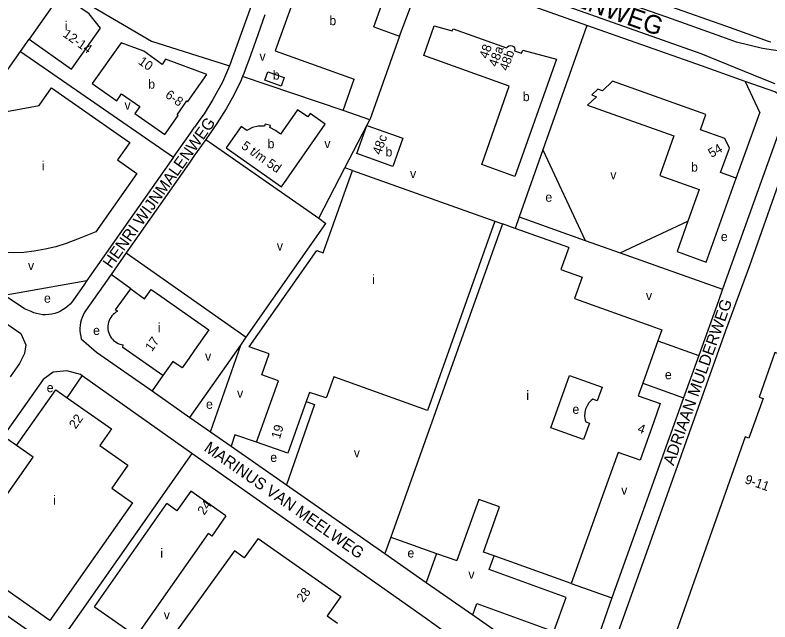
# Model space of a CAD drawing. Extents: x 154765 to 156627, y 383996 to 386132.
# Drawn here: x 155422.2 to 155749.2, y 384900.8 to 385163.7 of the extents above; entities that cross this region are included whole.
import ezdxf

# ---------------------------------------------------------------- set-up
doc = ezdxf.new("R2010")
doc.units = 0
for name, color, linetype in [('BLT_Basislijn', 7, 'Continuous'), ('BLT_Bebouwing', 7, 'Continuous'), ('BLT_Centroide', 7, 'Continuous'), ('BLT_Huisnummer', 7, 'Continuous'), ('BLT_Huisnummer_reeks', 7, 'Continuous'), ('BLT_Onderverdeling_panden', 7, 'Continuous'), ('BLT_Straatnaam', 7, 'Continuous'), ('BLT_Straatnaam_hoofdweg', 7, 'Continuous')]:
    doc.layers.add(name, color=color, linetype=linetype)

msp = doc.modelspace()

# ---------------------------------------------------------------- linework, layer by layer
at = {"layer": 'BLT_Basislijn'}
for p, q in [((155531.64, 385187.95), (155515.19, 385141.8)), ((155588.82, 385154.61), (155599.94, 385184.14)), ((155669.92, 385159.28), (155650.93, 385105.4)), ((155424.54, 385148.02), (155490.88, 385102.21)), ((155564.35, 385122.44), (155520.8, 385137.06)), ((155738.57, 385134.96), (155744.9, 385121.39)), ((155574.61, 385115.89), (155575.94, 385118.32)), ((155755.51, 385119.74), (155728.73, 385044.96)), ((155734.56, 385093.08), (155744.9, 385121.39)), ((155565.13, 385097.53), (155574.61, 385115.89)), ((155504.83, 385109.89), (155553.86, 385075.7)), ((155759.38, 385109.1), (155740.4, 385055.14)), ((155650.93, 385105.4), (155640.67, 385076.31)), ((155650.93, 385105.4), (155669.23, 385066.14)), ((155553.86, 385075.7), (155565.13, 385097.53)), ((155568.46, 385096.34), (155565.13, 385097.53)), ((155640.67, 385076.31), (155638.92, 385071.32)), ((155640.67, 385076.31), (155669.23, 385066.14)), ((155522.39, 385024.22), (155556.91, 385073.48)), ((155553.86, 385075.7), (155556.91, 385073.48)), ((155630.02, 385074.4), (155633.33, 385073.31)), ((155684.36, 385060.76), (155713.72, 385074.45)), ((155669.23, 385066.14), (155684.36, 385060.76)), ((155470.39, 385060.75), (155522.39, 385024.22)), ((155684.36, 385060.76), (155728.73, 385044.96)), ((155740.4, 385055.14), (155730.06, 385026.91)), ((155472.35, 385045.11), (155463.8, 385051.33)), ((155417.54, 385042.4), (155453.37, 385048.72)), ((155728.73, 385044.96), (155726.94, 385039.98)), ((155726.94, 385039.98), (155718.46, 385016.3)), ((155520, 385020.8), (155522.39, 385024.22)), ((155498, 384989.42), (155520, 385020.8)), ((155700.72, 385022.61), (155718.46, 385016.3)), ((155718.46, 385016.3), (155711.88, 384997.92)), ((155444.72, 384997.98), (155451.34, 385007.42)), ((155486.24, 385007.56), (155481.59, 385000.88)), ((155694.17, 385004.22), (155711.88, 384997.92)), ((155711.88, 384997.92), (155680.83, 384911.21)), ((155717.36, 384991.32), (155685.56, 384902.17)), ((155498, 384989.42), (155506.89, 384983.21)), ((155422.86, 384977.28), (155417.1, 384981.32)), ((155506.89, 384983.21), (155515.79, 384977)), ((155515.79, 384977), (155539.81, 384960.22)), ((155498.87, 384973.86), (155439.29, 384888.96)), ((155539.81, 384960.22), (155582.46, 384930.42)), ((155585.01, 384937.57), (155582.46, 384930.42)), ((155604.84, 384930.5), (155600.36, 384917.92)), ((155663.21, 384917.49), (155680.83, 384911.21)), ((155680.83, 384911.21), (155671.48, 384885.12))]:
    msp.add_line(p, q, dxfattribs=at)
for points in [[(155558.69, 385204.04), (155671.59, 385164), (155719.27, 385147.11), (155745.95, 385136.27), (155751.44, 385134.14)], [(155669.92, 385159.28), (155620.24, 385176.93), (155599.94, 385184.14)], [(155755.57, 385147.79), (155746.1, 385149.29), (155734.81, 385152.01), (155728.35, 385154.34), (155704.53, 385162.79), (155673.76, 385173.72)], [(155454.45, 385168.14), (155481.31, 385152.46), (155515.19, 385141.8)], [(155706.21, 385167.51), (155730.03, 385159.05), (155748.54, 385152.39), (155749.64, 385152.13)], [(155530.45, 385163.87), (155526.46, 385152.67), (155523.46, 385144.21), (155522.69, 385142.05)], [(155738.57, 385134.96), (155717.6, 385142.4), (155669.92, 385159.28)], [(155515.19, 385141.8), (155512.08, 385134.61), (155507.88, 385127.15), (155504.08, 385121.01), (155503.18, 385119.65), (155500, 385115.17)], [(155522.69, 385142.05), (155521.4, 385138.49), (155520.8, 385137.06)], [(155520.8, 385137.06), (155520.02, 385135.19), (155517.04, 385129.07), (155513.64, 385123.17), (155509.68, 385116.82)], [(155755.7, 385127.53), (155751.4, 385130.42), (155738.57, 385134.96)], [(155490.88, 385102.21), (155498.16, 385112.57), (155500, 385115.17)], [(155509.68, 385116.82), (155504.83, 385109.89)], [(155504.83, 385109.89), (155500, 385103)], [(155490.88, 385102.21), (155453.37, 385048.72)], [(155500, 385103), (155497.89, 385100), (155497.6, 385099.61), (155475.78, 385068.49), (155470.39, 385060.75)], [(155470.39, 385060.75), (155463.8, 385051.33)], [(155463.8, 385051.33), (155452.76, 385035.61)], [(155453.37, 385048.72), (155451.96, 385046.71), (155447.5, 385040.32)], [(155426.24, 385036.42), (155417.54, 385042.4)], [(155447.5, 385040.32), (155446.81, 385039.39), (155446.02, 385038.49), (155445.14, 385037.64), (155444.17, 385036.84), (155443.1, 385036.11), (155441.96, 385035.47), (155440.74, 385034.93), (155439.47, 385034.49), (155438.16, 385034.17), (155436.82, 385033.97), (155435.47, 385033.89), (155434.12, 385033.94), (155432.8, 385034.11), (155431.52, 385034.39), (155430.29, 385034.77), (155429.13, 385035.25), (155426.24, 385036.42)], [(155452.76, 385035.61), (155452.21, 385034.7), (155451.7, 385033.73), (155451.27, 385032.7), (155450.91, 385031.61), (155450.63, 385030.49), (155450.44, 385029.32), (155450.34, 385028.13), (155450.34, 385026.92), (155450.45, 385025.72), (155450.65, 385024.52), (155450.92, 385023.48)], [(155414.13, 385033.17), (155418.65, 385030.02), (155424.69, 385025.76), (155426.85, 385020.91), (155426.31, 385017.14), (155424.15, 385012.83), (155420.04, 385007.04)], [(155730.06, 385026.91), (155717.36, 384991.32)], [(155450.92, 385023.48), (155457.54, 385017.68), (155481.59, 385000.88)], [(155506.89, 384983.21), (155520, 385020.8)], [(155451.34, 385007.42), (155450.54, 385007.98), (155444.62, 385009.6), (155438.7, 385009.06), (155434.39, 385005.82), (155417.1, 384981.32)], [(155498.87, 384973.86), (155451.34, 385007.42)], [(155481.59, 385000.88), (155498, 384989.42)], [(155548.35, 384996.35), (155551.97, 384995.09), (155539.81, 384960.22)], [(155526.82, 384978.65), (155517.5, 384981.9), (155515.79, 384977)], [(155607.31, 384897.29), (155600, 384902.45), (155498.87, 384973.86)], [(155582.46, 384930.42), (155600.36, 384917.92)], [(155620.48, 384903.87), (155622.3, 384908.85), (155655.58, 384896.67), (155660.96, 384911.36), (155627.69, 384923.55), (155629.83, 384929.4)], [(155600.36, 384917.92), (155620.48, 384903.87)], [(155620.48, 384903.87), (155651.95, 384881.89)], [(155685.56, 384902.17), (155677.57, 384880.07), (155673.46, 384870.93), (155666.12, 384858.04)]]:
    msp.add_lwpolyline(points, dxfattribs=at)
at = {"layer": 'BLT_Bebouwing'}
for p, q in [((155599.26, 385146.25), (155603.8, 385159.03)), ((155603.8, 385159.03), (155611.64, 385156.96)), ((155611.64, 385156.96), (155611.95, 385157.79)), ((155400, 385113.29), (155424.54, 385148.02)), ((155534.94, 385148.2), (155569.18, 385136.03)), ((155642.14, 385148.51), (155656.82, 385144.69)), ((155636.29, 385132.98), (155599.26, 385146.25)), ((155624.37, 385098.99), (155636.29, 385132.98)), ((155638.8, 385093.86), (155624.37, 385098.99)), ((155741.73, 384984.41), (155741.74, 384984.4)), ((155456.67, 384907.42), (155487.98, 384952.08)), ((155492.36, 384949.02), (155487.98, 384952.08)), ((155513.59, 384946.77), (155507.46, 384938.03)), ((155507.46, 384938.03), (155505.97, 384939.07)), ((155527.47, 384937.04), (155521.5, 384928.6)), ((155527.47, 384937.04), (155541.11, 384927.49)), ((155517.23, 384931.68), (155485.23, 384887.36)), ((155521.5, 384928.6), (155517.23, 384931.68)), ((155541.11, 384927.49), (155563.37, 384911.88)), ((155563.37, 384911.88), (155557.44, 384903.43)), ((155557.44, 384903.43), (155561.85, 384900.33))]:
    msp.add_line(p, q, dxfattribs=at)
for points in [[(155577.59, 385158.61), (155581.82, 385170.48), (155574.93, 385172.93), (155575.55, 385174.67), (155553.22, 385182.59), (155551.44, 385182.95)], [(155428.3, 385153.34), (155446.72, 385140.34), (155459.18, 385158.04), (155454.27, 385164.27), (155442.01, 385172.85)], [(155542.97, 385170.82), (155534.94, 385148.2)], [(155577.59, 385158.61), (155588.82, 385154.61)], [(155611.95, 385157.79), (155635.18, 385149.48), (155635.51, 385149.99), (155636.14, 385150.43), (155636.95, 385150.58), (155637.59, 385150.43), (155638.16, 385150.05), (155638.54, 385149.5), (155638.7, 385148.82), (155638.63, 385148.24), (155641.65, 385147.16)], [(155588.82, 385154.61), (155575.94, 385118.32)], [(155424.54, 385148.02), (155428.3, 385153.34)], [(155468.14, 385151.74), (155455.67, 385134.02), (155466.24, 385126.61), (155468.35, 385129.61), (155476.24, 385124.07), (155474.13, 385121.07), (155487.09, 385111.95), (155492.83, 385120.16), (155492.42, 385120.45), (155496.68, 385126.52), (155497.09, 385126.24), (155505.27, 385137.93)], [(155505.27, 385137.93), (155487.45, 385144.59), (155485.93, 385142.38), (155478.07, 385148.08), (155468.14, 385151.74)], [(155641.65, 385147.16), (155642.14, 385148.51)], [(155656.82, 385144.69), (155638.8, 385093.86)], [(155564.35, 385122.44), (155569.18, 385136.03)], [(155734.56, 385093.08), (155727.91, 385095.51), (155731.69, 385106.03), (155729.74, 385110.24), (155719.12, 385114.03), (155721.45, 385120.7), (155681.04, 385135.1), (155676.67, 385130.92), (155674.66, 385131.64), (155672.13, 385129.15), (155674.13, 385128.38), (155670.19, 385124.72), (155707.61, 385111.35), (155701.5, 385094.26), (155718.59, 385088.15), (155713.72, 385074.45)], [(155400, 385104.36), (155411.43, 385120.68), (155432.67, 385124.51), (155438.05, 385132.17), (155467.8, 385111.44), (155471.9, 385108.58), (155466.59, 385100.99), (155474.93, 385095.15), (155457.22, 385069.83), (155449.21, 385066.66), (155444.34, 385064.78), (155439.85, 385063.36), (155435.29, 385062.31), (155430.51, 385061.49), (155425.98, 385060.94), (155421.34, 385060.7), (155415.6, 385060.82), (155407.39, 385061.04), (155400, 385066.22)], [(155556.6, 385116.46), (155550.12, 385121.11), (155549.06, 385119.62), (155544.65, 385122.72), (155537.25, 385112.15), (155535.03, 385113.71), (155532.59, 385115.02), (155532.82, 385115.92), (155530.57, 385116.49), (155530.34, 385115.58), (155527.58, 385115.59), (155525.05, 385115), (155522.7, 385113.79), (155520.24, 385115.51), (155513.68, 385106.18)], [(155575.94, 385118.32), (155564.35, 385122.44)], [(155513.68, 385106.18), (155537.67, 385089.36), (155556.6, 385116.46)], [(155526.82, 384978.65), (155536.34, 385005.32), (155529.1, 385007.89), (155532.32, 385016.92), (155523.71, 385020.02), (155553.01, 385061.73), (155555.77, 385060.74), (155568.46, 385096.34)], [(155568.46, 385096.34), (155630.02, 385074.4)], [(155721.61, 385056.68), (155734.56, 385093.08)], [(155630.02, 385074.4), (155600.84, 384992.48), (155560.29, 385006.95), (155557.42, 384998.96), (155557.05, 384997.91), (155549.74, 385000.25), (155548.35, 384996.35)], [(155633.33, 385073.31), (155585.01, 384937.57)], [(155638.92, 385071.32), (155633.33, 385073.31)], [(155713.72, 385074.45), (155709.03, 385061.25), (155721.61, 385056.68)], [(155662.07, 385063.08), (155638.92, 385071.32)], [(155662.07, 385063.08), (155658.67, 385053.54), (155667.97, 385050.22), (155664.65, 385040.89), (155697.72, 385029.07), (155702.43, 385027.39), (155700.72, 385022.61)], [(155466.6, 385035.36), (155465.73, 385036), (155472.35, 385045.11)], [(155472.35, 385045.11), (155478.29, 385040.79), (155481.22, 385044.81), (155485.32, 385041.94), (155500, 385031.65), (155506.17, 385027.32), (155500, 385018.51), (155497.5, 385014.95), (155494.63, 385010.85), (155490.53, 385013.72), (155486.24, 385007.56)], [(155762.36, 385042.82), (155753.18, 385017), (155751.43, 385017.62), (155744.64, 384998.23), (155746.3, 384997.64), (155740.17, 384980.4), (155738.59, 384980.96), (155696.77, 384862.93)], [(155466.6, 385035.36), (155465.92, 385034.97), (155465.29, 385034.51), (155464.7, 385033.99), (155464.17, 385033.41), (155463.69, 385032.78), (155463.29, 385032.11), (155462.96, 385031.4), (155462.7, 385030.66), (155462.51, 385029.89), (155462.41, 385029.12), (155462.38, 385028.33), (155462.44, 385027.55), (155462.57, 385026.77), (155462.79, 385026.02), (155463.07, 385025.29), (155463.43, 385024.59), (155463.87, 385023.93), (155464.36, 385023.32), (155464.91, 385022.77), (155465.52, 385022.27), (155466.18, 385021.84), (155466.87, 385021.47), (155467.6, 385021.18), (155468.36, 385020.97), (155469.03, 385020.84)], [(155486.24, 385007.56), (155468.91, 385019.67), (155469.03, 385020.84)], [(155700.72, 385022.61), (155694.17, 385004.22)], [(155669.45, 384987.57), (155671.08, 384986.96), (155668.55, 384979.8), (155654.33, 384984.85), (155662.39, 385007.58), (155676.58, 385002.55), (155674.46, 384996.55), (155672.6, 384997.28)], [(155694.17, 385004.22), (155692.67, 385000), (155692.24, 384998.8), (155701.77, 384995.41), (155698.94, 384987.5), (155693.01, 384970.89), (155683.48, 384974.23), (155677.32, 384957.01), (155663.21, 384917.49)], [(155422.86, 384977.28), (155439.82, 385001.42)], [(155439.82, 385001.42), (155444.72, 384997.98)], [(155444.72, 384997.98), (155463.95, 384984.47), (155458.92, 384977.32), (155471.07, 384968.79), (155464.07, 384958.83), (155473.14, 384952.46), (155437.27, 384901.4), (155412.17, 384919.04), (155417.32, 384926.36), (155404.26, 384935.53), (155430.04, 384972.23), (155422.86, 384977.28)], [(155672.6, 384997.28), (155671.87, 384996.76), (155670.87, 384995.73), (155670.01, 384994.48), (155669.35, 384992.94), (155669.02, 384991.49), (155668.95, 384989.96), (155669.21, 384988.28), (155669.45, 384987.57)], [(155548.35, 384996.35), (155540.35, 384973.93), (155526.82, 384978.65)], [(155513.59, 384946.77), (155498.3, 384957.49), (155492.36, 384949.02)], [(155629.83, 384929.4), (155625.14, 384931.07), (155632.16, 384950.76), (155623.21, 384953.94), (155613.59, 384927.39)], [(155456.67, 384907.42), (155474.83, 384894.65), (155505.97, 384939.07)], [(155585.01, 384937.57), (155604.84, 384930.5)], [(155604.84, 384930.5), (155613.59, 384927.39)], [(155663.21, 384917.49), (155629.83, 384929.4)], [(155439.29, 384888.96), (155399.36, 384917.11)]]:
    msp.add_lwpolyline(points, dxfattribs=at)
for points in [[(155530.4, 385135.47), (155531.74, 385139.17), (155538.86, 385136.63), (155537.52, 385132.91)], [(155574.61, 385115.89), (155590.21, 385110.34), (155585.86, 385098.13), (155570.26, 385103.71)]]:
    msp.add_lwpolyline(points, close=True, dxfattribs=at)
at = {"layer": 'BLT_Onderverdeling_panden'}
msp.add_line((155442.01, 385172.85), (155428.3, 385153.34), dxfattribs=at)

# ---------------------------------------------------------------- texts
at = {"layer": 'BLT_Centroide'}
for s, p in [('i', (155443.73, 385157.05)), ('b', (155558.38, 385159.36)), ('v', (155528.1, 385143.93)), ('b', (155533.89, 385135.78)), ('b', (155479.9, 385131.84)), ('b', (155642.17, 385126.44)), ('v', (155469.62, 385122.8)), ('b', (155531.6, 385106.03)), ('v', (155556.2, 385106.09)), ('b', (155582.71, 385102.5)), ('i', (155433.77, 385096.44)), ('b', (155715.07, 385095.91)), ('v', (155593.32, 385093.08)), ('v', (155680.08, 385092.59)), ('e', (155651.97, 385082.86)), ('e', (155727.99, 385065.81)), ('v', (155535.63, 385061.73)), ('v', (155427.8, 385053.29)), ('i', (155576.86, 385047.19)), ('v', (155695.52, 385040.23)), ('e', (155434.73, 385039.11)), ('i', (155484.09, 385026.34)), ('e', (155456.02, 385025.16)), ('v', (155504.53, 385013.95)), ('e', (155703.74, 385005.96)), ('e', (155435.92, 385000.36)), ('v', (155518.38, 384997.94)), ('i', (155643.72, 384997.03)), ('e', (155504.94, 384993.17)), ('e', (155663.69, 384990.99)), ('v', (155568.97, 384972.16)), ('e', (155532.78, 384970.14)), ('v', (155684.82, 384955.98)), ('i', (155438.7, 384951.64)), ('i', (155485.12, 384928.69)), ('e', (155592.21, 384928.73)), ('v', (155618.6, 384919.51)), ('v', (155486.63, 384901.96))]:
    msp.add_text(s, height=4, dxfattribs=at).set_placement(p)
at = {"layer": 'BLT_Huisnummer'}
for s, rotation, p in [('48c', 70.5506, (155580.66, 385102.93)), ('54', 30.2358, (155723.95, 385101.81)), ('17', 55.1455, (155481.5, 385017.67)), ('22', 54.915, (155448.49, 384984.17)), ('19', 73.4214, (155536.93, 384979.86)), ('4', 340.6859, (155691.61, 384983.12)), ('24', 54.9362, (155504.15, 384946.83)), ('28', 54.4456, (155547.06, 384909.04))]:
    msp.add_text(s, height=4, rotation=rotation, dxfattribs=at).set_placement(p)
at = {"layer": 'BLT_Huisnummer_reeks'}
for s, rotation, p in [('12-14', 324.7896, (155442.6, 385154.71)), ('48', 70.5506, (155626.93, 385144.58)), ('48a', 70.5506, (155630.97, 385141.01)), ('48b', 70.5506, (155635.67, 385139.31)), ('10', 324.9524, (155475.3, 385142.84)), ('6-8', 324.8868, (155486.95, 385128.36)), ('5 t/m 5d', 324.963, (155519.92, 385106.24)), ('9-11', 340.6859, (155738.07, 384960.99))]:
    msp.add_text(s, height=4, rotation=rotation, dxfattribs=at).set_placement(p)
at = {"layer": 'BLT_Straatnaam'}
for s, rotation, p in [('HENRI WIJNMALENWEG', 54.4808, (155463.93, 385053.66)), ('ADRIAAN MULDERWEG', 70.3697, (155707.51, 384968.27)), ('MARINUS VAN MEELWEG', 324.9485, (155503.71, 384975.26))]:
    msp.add_text(s, height=5, rotation=rotation, dxfattribs=at).set_placement(p)
at = {"layer": 'BLT_Straatnaam_hoofdweg'}
msp.add_text('LUCHTHAVENWEG', height=8, rotation=340.4457, dxfattribs=at).set_placement((155608.83, 385187.42))

doc.saveas('drawing.dxf')
